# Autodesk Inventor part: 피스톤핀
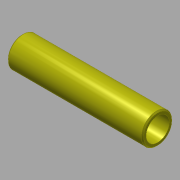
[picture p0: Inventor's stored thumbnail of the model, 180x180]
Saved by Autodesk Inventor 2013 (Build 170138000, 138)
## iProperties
Created: 2016-11
Part Number: 피스톤핀
Material: 강철, 탄소
Document SubType Name: Modeling
Designer: mduedu
Density: 7.87 g/cm^3
Mass: 24.6584 g
Surface Area: 42.7469 cm^2
Volume: 3.13322 cm^3
Author: mduedu
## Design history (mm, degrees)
sketch "스케치1"
  geometry: C1 r 5 at (0, 0); C2 r 6.5 at (0, 0); 1 further point
  constraints: 2 centre point, 2 coincident
  dimensions: "d0" = 10 diameter of C1; "d1" = 13 diameter of C2
extrude "돌출1" new body sketch "스케치1" stored distance "d2" = 58; taper "d3" = 0 deg
chamfer "모따기1" distance "d4" = 0.5; stored, may be unused: second distance "d5" = 2, angle "d6" = 45 deg
node "솔리드1"
